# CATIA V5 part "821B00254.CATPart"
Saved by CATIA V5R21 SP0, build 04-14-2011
Part number: 821B00254
Bounding box of the stored display mesh (mm): x -25.55 to 25.548, y -6.5 to 6.5, z -127 to 127
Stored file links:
  C:\Users\ALI OZGUN\Desktop\alhan\821B00254.CATPart
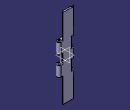
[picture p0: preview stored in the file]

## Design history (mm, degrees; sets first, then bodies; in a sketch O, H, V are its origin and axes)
Body1 (main body)
  Sketch1 on xy-plane, origin (0, 0, 0), H (1, 0, 0), V (0, 1, 0)
    construction line L1 (-19.05, 0) -> (19.05, 0)
    point P1 (-19.05, 0)
    line L2 (-19.05, 6.5) -> (19.05, 6.5)
    line L3 (19.05, -6.5) -> (-19.05, -6.5)
    arc A1 centre (19.05, 0) radius 6.5 from (19.05, 6.5) to (19.05, -6.5) cw
    arc A2 centre (-19.05, 0) radius 6.5 from (-19.05, -6.5) to (-19.05, 6.5) cw
    distance L1 L2 = 6.5
    length L1 = 38.1
    distance V P1 = 19.05
    coincidence: P1 H
    horizontal: L1 H
    tangency: A1 L2, A2 L2, A1 L3, A2 L3
  Pad1: profile Sketch1, direction (0, 0, 1), length 95.25, mirrored extent
  Sketch2 on face of Pad1 from Sketch1.L3, origin (19.05, -6.5, 0), H (-1, 0, 0), V (0, 0, 1)
    line L1 (-52.6725, 130.3302) -> (77.8049, 130.3302)
    line L2 (77.8049, 130.3302) -> (77.8049, -110.1365)
    line L3 (77.8049, -110.1365) -> (-52.6725, -110.1365)
    line L4 (-52.6725, -110.1365) -> (-52.6725, 130.3302)
    horizontal: L1 H, L3 H
    vertical: L2 V, L4 V
  Pocket1: profile Sketch2, direction (0, 1, 0), length 8
  Sketch3 on end face of Pad1, origin (0, 0, 95.25), H (1, 0, 0), V (0, 1, 0)
    arc A1 centre (19.05, 0) radius 6.5 from (12.55, 0) to (19.05, 6.5) ccw
    point P1 (19.05, 0)
    arc A2 centre (-19.05, 0) radius 6.5 from (-19.05, 6.5) to (-12.55, 0) ccw
    reference projected arc E1 centre (19.05, 0) radius 6.5 from (19.05, -6.5) to (19.05, 6.5) ccw from edge [face of Pad1 from Sketch1.A1 | end face of Pad1]
    reference projected arc E2 centre (19.05, 0) radius 6.5 from (19.05, -6.5) to (19.05, 6.5) ccw from edge [face of Pad1 from Sketch1.A1 | end face of Pad1]
    reference projected arc E3 centre (-19.05, 0) radius 6.5 from (-19.05, 6.5) to (-19.05, -6.5) ccw from edge [face of Pad1 from Sketch1.A2 | end face of Pad1]
    line L1 (-19.05, 6.5) -> (19.05, 6.5)
    line L2 (12.55, 0) -> (12.55, 1.5)
    point P3 (12.55, 0)
    line L3 (-12.55, 0) -> (-12.55, 1.5)
    point P4 (-12.55, 0)
    projected line E4 (-25.3746, 1.5) -> (25.3746, 1.5) from edge [end face of Pocket1 | end face of Pad1]
    projected line E5 (-12.55, 1.5) -> (12.55, 1.5) from edge [end face of Pocket1 | end face of Pad1]
    coincidence: P1 H, A1 E2, A2 E3, P3 A1, P3 H, P4 A2, P4 H, P3 L2, P4 L3
    concentricity: A1 E1
    tangency: L1 A1, L2 A1, L3 A2, L1 A2
  Pad2: profile Sketch3, direction (0, 0, -1), up to start face of Pad1
  Sketch4 on face of Pad1 from Sketch1.L2, origin (0, 6.5, 0), H (-1, 0, 0), V (0, 0, 1)
    line L1 (-39.6469, 109.6787) -> (-14.25, 109.6787)
    line L2 (-14.25, 109.6787) -> (-14.25, 47.8)
    line L3 (-14.25, 47.8) -> (-39.6469, 47.8)
    line L4 (-39.6469, 47.8) -> (-39.6469, 109.6787)
    point P5 (-39.6469, 15)
    line L5 (-39.6469, 15) -> (-14.25, 15)
    line L6 (-14.25, 15) -> (-14.25, -15)
    line L7 (-14.25, -15) -> (-39.6469, -15)
    line L8 (-39.6469, -15) -> (-39.6469, 15)
    point P7 (-14.25, -15)
    point P9 (-39.6469, -47.8)
    line L9 (-39.6469, -47.8) -> (-14.25, -47.8)
    line L10 (-14.25, -47.8) -> (-14.25, -127.278)
    line L11 (-14.25, -127.278) -> (-39.6469, -127.278)
    line L12 (-39.6469, -127.278) -> (-39.6469, -47.8)
    point P11 (-14.25, -127.278)
    line L13 (14.25, 48.3) -> (41.1409, 48.3)
    line L14 (41.1409, 48.3) -> (41.1409, 14.5)
    line L15 (41.1409, 14.5) -> (14.25, 14.5)
    line L16 (14.25, 14.5) -> (14.25, 48.3)
    line L17 (14.25, -14.5) -> (41.1409, -14.5)
    line L18 (41.1409, -14.5) -> (41.1409, -48.3)
    line L19 (41.1409, -48.3) -> (14.25, -48.3)
    line L20 (14.25, -48.3) -> (14.25, -14.5)
    point P19 (41.1409, -48.3)
    line L21 (27.5155, 68.3) -> (25.05, 68.3)
    point P21 (25.05, 68.3)
    line L22 (25.05, 68.3) -> (23.779, 141.1156)
    point P22 (23.779, 141.1156)
    reference projected line E1 through (19.05, 0) direction (0, 1) from axis of face of Pad1 from Sketch1.A2
    line L23 (23.779, 141.1156) -> (27.5155, 141.1156)
    point P23 (27.5155, 141.1156)
    line L24 (27.5155, 141.1156) -> (27.5155, 68.3)
    point P24 (27.5155, 68.3)
    point P25 (25.05, -68.3)
    point P26 (23.779, -141.1156)
    point P27 (27.5155, -141.1156)
    point P28 (27.5155, -68.3)
    line L25 (27.5155, -68.3) -> (25.05, -68.3)
    line L26 (25.05, -68.3) -> (23.779, -141.1156)
    line L27 (23.779, -141.1156) -> (27.5155, -141.1156)
    line L28 (27.5155, -141.1156) -> (27.5155, -68.3)
    distance L6 L20 = 28.5
    distance L16 V = 14.25
    distance L13 L15 = 33.8
    distance L17 L19 = 33.8
    distance L17 L15 = 29
    distance L17 H = 14.5
    distance L7 L9 = 32.8
    distance L5 L3 = 32.8
    distance L5 L7 = 30
    distance L7 H = 15
    distance L21 L13 = 20
    distance P21 E1 = 6
    angle L22 V = 1
    horizontal: L1 H, L3 H, L5 H, L7 H, L9 H, L11 H, L13 H, L15 H, L17 H, L19 H, L21 H, L23 H
    vertical: L2 V, L4 V, L6 V, L8 V, L10 V, L12 V, L14 V, L16 V, L18 V, L20 V, L24 V
    coincidence: P5 L4, P7 L2, P9 L4, P11 L2, P19 L14, L20 L16
    symmetry: P21 P25 H, P22 P26 H, P23 P27 H, P24 P28 H, L21 L25 H, L22 L26 H, L23 L27 H, L24 L28 H
  Pocket2: profile Sketch4, direction (0, -1, 0), length 95.25
  Sketch5 on zx-plane, origin (0, 0, 0), H (-1, 0, 0), V (0, 0, 1)
    point P1 (50.8802, 124.1518)
    line L1 (50.8802, 124.1518) -> (7.4864, 124.1518)
    line L2 (7.4864, 124.1518) -> (7.4864, 68.3)
    line L3 (7.4864, 68.3) -> (50.8802, 68.3)
    line L4 (50.8802, 68.3) -> (50.8802, 124.1518)
    point P2 (7.4864, 124.1518)
    point P3 (7.4864, 68.3)
    point P4 (50.8802, 68.3)
    reference projected line E1 (25.55, 68.3) -> (25.05, 68.3) from edge [face of Pocket2 from Sketch4.L21 | face of Pad2 from Sketch3.A2]
    point P5 (50.8802, -124.1518)
    point P6 (7.4864, -124.1518)
    point P7 (7.4864, -68.3)
    point P8 (50.8802, -68.3)
    line L5 (50.8802, -124.1518) -> (7.4864, -124.1518)
    line L6 (7.4864, -124.1518) -> (7.4864, -68.3)
    line L7 (7.4864, -68.3) -> (50.8802, -68.3)
    line L8 (50.8802, -68.3) -> (50.8802, -124.1518)
    point P9 (-40.2009, 47.8)
    line L9 (-40.2009, 47.8) -> (-4.3891, 47.8)
    line L10 (-4.3891, 47.8) -> (-4.3891, 101.6633)
    line L11 (-4.3891, 101.6633) -> (-40.2009, 101.6633)
    line L12 (-40.2009, 101.6633) -> (-40.2009, 47.8)
    point P10 (-4.3891, 47.8)
    point P11 (-4.3891, 101.6633)
    point P12 (-40.2009, 101.6633)
    point P13 (32.704, 48.3)
    line L13 (32.704, 48.3) -> (5.2293, 48.3)
    line L14 (5.2293, 48.3) -> (5.2293, 14.5)
    line L15 (5.2293, 14.5) -> (32.704, 14.5)
    line L16 (32.704, 14.5) -> (32.704, 48.3)
    point P14 (5.2293, 48.3)
    point P15 (5.2293, 14.5)
    point P16 (32.704, 14.5)
    line L17 (-8.2283, 15) -> (-32.8228, 15)
    line L18 (-32.8228, 15) -> (-32.8228, -15)
    line L19 (-32.8228, -15) -> (-8.2283, -15)
    line L20 (-8.2283, -15) -> (-8.2283, 15)
    reference projected line E2 (-25.55, -15) -> (-14.25, -15) from edge [face of Pocket2 from Sketch4.L7 | face of Pad2 from Sketch3.A1]
    reference projected line E3 (-14.25, 15) -> (-25.55, 15) from edge [face of Pocket2 from Sketch4.L5 | face of Pad2 from Sketch3.A1]
    reference projected line E4 (14.25, 14.5) -> (25.55, 14.5) from edge [face of Pocket2 from Sketch4.L15 | face of Pad2 from Sketch3.A2]
    reference projected line E5 (-25.55, 47.8) -> (-14.25, 47.8) from edge [face of Pocket2 from Sketch4.L3 | face of Pad2 from Sketch3.A1]
    reference projected line E6 (25.55, 48.3) -> (14.25, 48.3) from edge [face of Pocket2 from Sketch4.L13 | face of Pad2 from Sketch3.A2]
    point P21 (32.704, -48.3)
    point P22 (5.2293, -48.3)
    point P23 (5.2293, -14.5)
    point P24 (32.704, -14.5)
    line L21 (32.704, -48.3) -> (5.2293, -48.3)
    line L22 (5.2293, -48.3) -> (5.2293, -14.5)
    line L23 (5.2293, -14.5) -> (32.704, -14.5)
    line L24 (32.704, -14.5) -> (32.704, -48.3)
    point P25 (-40.2009, -47.8)
    point P26 (-4.3891, -47.8)
    point P27 (-4.3891, -101.6633)
    point P28 (-40.2009, -101.6633)
    line L25 (-40.2009, -47.8) -> (-4.3891, -47.8)
    line L26 (-4.3891, -47.8) -> (-4.3891, -101.6633)
    line L27 (-4.3891, -101.6633) -> (-40.2009, -101.6633)
    line L28 (-40.2009, -101.6633) -> (-40.2009, -47.8)
    horizontal: L1 H, L3 H, L9 H, L11 H, L13 H, L15 H, L17 H, L19 H
    vertical: L2 V, L4 V, L10 V, L12 V, L14 V, L16 V, L18 V, L20 V
    coincidence: L3 E1, L19 E2, L17 E3, L15 E4, L9 E5, L13 E6
    symmetry: P1 P5 H, P2 P6 H, P3 P7 H, P4 P8 H, L1 L5 H, L2 L6 H, L3 L7 H, L4 L8 H, P13 P21 H, P14 P22 H, P15 P23 H, P16 P24 H, L13 L21 H, L14 L22 H, L15 L23 H, L16 L24 H, P9 P25 H, P10 P26 H, P11 P27 H, P12 P28 H, L9 L25 H, L10 L26 H, L11 L27 H, L12 L28 H
  Pocket3: profile Sketch5, direction (0, -1, 0), length 8.2, opposite side up to end face of Pocket1
  Sketch6 on xy-plane, origin (0, 0, 0), H (1, 0, 0), V (0, 1, 0)
    circle A1 centre (-19.05, 0) radius 3.25
    point P1 (-19.05, 0)
    circle A2 centre (19.05, 0) radius 3.25
    point P2 (19.05, 0)
    reference projected arc E1 centre (19.05, 0) radius 6.5 from (12.55, 0) to (19.05, 6.5) ccw from edge [face of Pocket2 | face of Pad1]
    reference projected arc E2 centre (-19.05, 0) radius 6.5 from (-25.05, 2.5) to (-12.55, 0) ccw from edge [face of Pocket2 | face of Pad1]
    radius A2 = 3.25
    radius A1 = 3.25
    coincidence: P1 H, P2 H
    concentricity: P2 E1, P1 E2
  Pocket4: profile Sketch6, direction (0, 0, -1), length 139.2, mirrored extent
  Sketch7 on face of Pocket2, origin (0, 0, -68.3), H (1, 0, 0), V (0, -1, 0)
    circle A1 centre (-19.05, 0) radius 4.5
    reference projected arc E1 centre (-19.05, 0) radius 3.25 from (-16.2801, -1.7) to (-21.8199, -1.7) ccw from edge [face of Pocket2 | face of Pocket4 from Sketch6.A1]
    radius A1 = 4.5
    concentricity: A1 E1
  Pocket5: profile Sketch7, direction (0, 0, -1), length 139.2
  Mirror1: of Pocket5, Sketch7, about xy-plane
  Sketch8 on face of Pocket2, origin (0, 0, -14.5), H (1, 0, 0), V (0, -1, 0)
    arc A1 centre (-15.5728, -1.6782) radius 5 from (-14.25, -6.5) to (-10.576, -1.5) ccw
    point P2 (-14.25, -6.5)
    point P3 (-10.576, -1.5)
    reference projected line E1 (-12.55, -1.5) -> (-12.55, 0) from edge [face of Pad2 from Sketch3.L3 | face of Pocket2]
    reference projected line E2 (-12.55, -1.5) -> (12.55, -1.5) from edge [face of Pad2 | face of Pad1]
    reference projected line E3 (19.05, -6.5) -> (-19.05, -6.5) from edge [face of Pad2 | face of Pad1]
    reference projected line E4 (-14.25, -6.5) -> (-14.25, 88.75) from edge [face of Pocket2 from Sketch4.L20 | face of Pocket2]
    distance P3 E1 = 1.974
    radius A1 = 5
    coincidence: P3 E2, P2 E3, P2 E4
  Pocket6: profile Sketch8, direction (0, 0, -1), length 33.8
  Mirror2: of Pocket6, Sketch8, about xy-plane
  Sketch9 on face of Pocket2, origin (0, 0, 15), H (1, 0, 0), V (0, -1, 0)
    reference projected arc E1 centre (-15.5728, -1.6782) radius 5 from (-14.25, -6.5) to (-10.576, -1.5) ccw from Sketch8
    point P1 (-14.25, -6.5)
    point P2 (-10.576, -1.5)
    point P3 (14.25, -6.5)
    point P4 (10.576, -1.5)
    arc A1 centre (15.5728, -1.6782) radius 5 from (14.25, -6.5) to (10.576, -1.5) cw
    symmetry: P1 P3 V, P2 P4 V, E1 A1 V
  Pocket7: profile Sketch9, direction (0, 0, -1), length 30
  Pocket8: profile Sketch9, direction (0, 0, 1), length 88, opposite side length -32.8
  Mirror3: of Pocket8, Sketch9, about xy-plane
  Sketch10 on face of Pad2, origin (0, 1.5, 0), H (1, 0, 0), V (0, 0, 1)
    line L1 (-19.05, 49.9703) -> (19.05, 42.4604)
    line L2 (19.05, 46.1297) -> (-19.05, 53.6396)
    reference projected point E1 (-10.576, 48.3) from vertex [face of Mirror2 | face of Mirror2 | face of Pad2]
    reference projected point E2 (10.576, 47.8) from vertex [face of Pocket8 from Sketch9.A1 | start face of Pocket8 | face of Pad2]
    line L3 (19.05, 46.1297) -> (19.05, 42.4604)
    line L4 (-19.05, 53.6396) -> (-19.05, 49.9703)
    reference projected line E3 through (19.05, 0) direction (0, 1) from axis of face of Pad1
    reference projected line E4 through (-19.05, 0) direction (0, 1) from axis of face of Pad1
    point P1 (19.05, 42.4604)
    point P2 (19.05, 46.1297)
    point P3 (-19.05, 53.6396)
    point P4 (-19.05, 49.9703)
    point P5 (19.05, -42.4604)
    point P6 (19.05, -46.1297)
    point P7 (-19.05, -53.6396)
    point P8 (-19.05, -49.9703)
    line L5 (-19.05, -49.9703) -> (19.05, -42.4604)
    line L6 (19.05, -46.1297) -> (-19.05, -53.6396)
    line L7 (19.05, -46.1297) -> (19.05, -42.4604)
    line L8 (-19.05, -53.6396) -> (-19.05, -49.9703)
    distance L2 L1 = 3.6
    distance L3 E3 = 0
    distance L4 E4 = 0
    coincidence: L1 E1, L2 E2
    vertical: L3 V, L4 V
    symmetry: P1 P5 H, P2 P6 H, P3 P7 H, P4 P8 H, L1 L5 H, L2 L6 H, L3 L7 H, L4 L8 H
  Pad3: profile Sketch10, direction (0, -1, 0), length 8
  Sketch11 on face of Mirror1, origin (0, 0, 68.3), H (1, 0, 0), V (0, 1, 0)
    projected circle E1 centre (-19.05, 0) radius 3.25 from edge [face of Pocket4 from Sketch6.A1 | face of Mirror1]
    projected circle E2 centre (19.05, 0) radius 3.25 from edge [face of Pocket4 from Sketch6.A2 | start face of Pocket8]
  Pocket9: profile Sketch11, direction (0, 0, -1), length 189
  Thickness1: Face (face of Pad1; face of Pad1), Thickness 31.75
  Thickness2: Face (face of Pocket5; face of Mirror1), Thickness 0.2
Body2
  Solid1: linked copy from another document
  Translate1: Direction yz-plane, Length 38.1, ToTransfor Solid1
